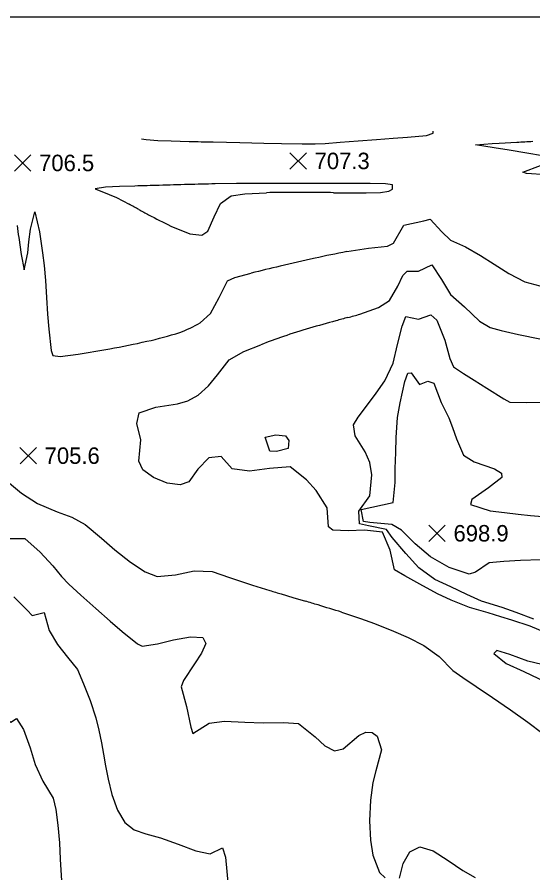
# Model space of a CAD drawing. Extents: x 2566079 to 2571326, y 424054 to 426896.
# Drawn here: x 2567271 to 2567741, y 426094 to 426874 of the extents above; entities that cross this region are included whole.
import ezdxf

# ---------------------------------------------------------------- set-up
doc = ezdxf.new("R2010")
doc.units = 0
for name, color, linetype in [('Contour_ADS_Major', 7, 'Continuous'), ('Contour_ADS_Minor', 7, 'Continuous'), ('Contour_ADS_Spot_Elevation', 7, 'Continuous'), ('Contour_ADS_State_Plane_Border', 7, 'Continuous')]:
    doc.layers.add(name, color=color, linetype=linetype)

# ---------------------------------------------------------------- blocks, each defined once
blk = doc.blocks.new('S750')
at = {"layer": 'Contour_ADS_Spot_Elevation'}
for p, q in [((-0.5, 0.498), (0.5, -0.498)), ((-0.498, -0.5), (0.498, 0.5))]:
    blk.add_line(p, q, dxfattribs=at)

msp = doc.modelspace()

# ---------------------------------------------------------------- linework, layer by layer
at = {"layer": 'Contour_ADS_Major'}
for points in [[(2567748.41, 426379.26), (2567729.86, 426378.59), (2567714.78, 426377.68), (2567701.34, 426376.28), (2567688.89, 426367.92), (2567683.13, 426366.09), (2567664.8, 426372.2), (2567648.02, 426381.8), (2567633.96, 426393.79), (2567621.58, 426406.17), (2567612.59, 426411.45), (2567592.69, 426413.15), (2567586.82, 426414.17), (2567584.76, 426424.92), (2567604.26, 426429.16), (2567614.04, 426431.53), (2567615.6, 426449.49), (2567615.84, 426462.31), (2567616.24, 426477.04), (2567616.73, 426490.71), (2567617.98, 426508.85), (2567620.14, 426522.36), (2567624.39, 426541.56), (2567627.16, 426549.24), (2567630.41, 426549.57), (2567637.76, 426539.03), (2567645.55, 426542.01), (2567650.8, 426540.1), (2567657.55, 426522.56), (2567664.63, 426508.58), (2567668.06, 426499.63), (2567671.74, 426489.33), (2567678, 426474.51), (2567687.66, 426468.49), (2567706.3, 426461.96), (2567712.56, 426458.11), (2567712.87, 426454.04), (2567700.6, 426444.81), (2567685.64, 426434.17), (2567684.49, 426429.59), (2567702.15, 426423.9), (2567715.37, 426422.15), (2567727.71, 426420.68), (2567739.05, 426419.5), (2567749.91, 426418.72)], [(2567268.29, 426345.26), (2567280.58, 426333.38), (2567284.99, 426328.32), (2567295.82, 426331.06), (2567300.41, 426314.84), (2567308.06, 426302), (2567317.11, 426290.53), (2567326.3, 426279.11), (2567331.89, 426266), (2567337.97, 426250.85), (2567343.07, 426235.01), (2567345.79, 426223.82), (2567348.15, 426212.42), (2567349.95, 426201.91), (2567351.71, 426191.36), (2567354.11, 426179.35), (2567357.74, 426165.16), (2567362.82, 426150.97), (2567369.48, 426139.68), (2567377.92, 426133.21), (2567388.58, 426129.56), (2567401.97, 426125.78), (2567417.99, 426119.91), (2567434.11, 426114.04), (2567447.18, 426111.28), (2567458.53, 426116.64), (2567461.16, 426108.06), (2567462.34, 426095.16), (2567463.66, 426081.33)]]:
    msp.add_lwpolyline(points, dxfattribs=at)
at = {"layer": 'Contour_ADS_Minor'}
for points in [[(2567439.01, 426760.22), (2567449.96, 426759.97), (2567462.05, 426759.7), (2567474.13, 426759.42), (2567485.11, 426759.18), (2567496.09, 426758.93), (2567512.31, 426758.56), (2567530.95, 426758.13), (2567542.91, 426758.18), (2567551.98, 426758.7), (2567565.51, 426759.71), (2567581.91, 426761), (2567598.77, 426762.31), (2567614.03, 426763.42), (2567626.94, 426764.34), (2567644.18, 426765.85), (2567650.33, 426767.9), (2567650.27, 426769.9)], [(2567384.57, 426762.75), (2567388.75, 426762.28), (2567399.59, 426761.44), (2567411.79, 426760.91), (2567428.07, 426760.48)], [(2567750.01, 426747.43), (2567735.7, 426749.77), (2567719.59, 426752.41), (2567705.95, 426754.66), (2567688.79, 426757.36), (2567704.02, 426758.63), (2567710.41, 426758.93), (2567726.65, 426759.79)], [(2567753.18, 426729.87), (2567735.26, 426731.27), (2567731.91, 426732.44), (2567748.19, 426738.36)], [(2567538.47, 426722.14), (2567510.23, 426722.14), (2567488.88, 426722.13), (2567471.17, 426722.04), (2567451.73, 426721.73)], [(2567570.82, 426713.59), (2567589.2, 426713.49), (2567602.43, 426713.95), (2567610.01, 426715.2), (2567613.32, 426716.88), (2567613.43, 426721.04), (2567606.86, 426721.81), (2567593.05, 426722.03)], [(2567351.86, 426718.71), (2567342.34, 426717.13), (2567355.31, 426712.17), (2567361.86, 426709.23), (2567373.32, 426703.27)], [(2567378.56, 426719.76), (2567364.48, 426719.3), (2567351.86, 426718.71), (2567351.86, 426718.71)], [(2567411.21, 426683.35), (2567428.63, 426676.2), (2567439.45, 426675.07), (2567445.06, 426678.72), (2567450.86, 426691.71), (2567456.61, 426703.77), (2567466.41, 426710.9), (2567478.61, 426712.73), (2567498.4, 426713.69)], [(2567272.78, 426672.96), (2567275.05, 426657.54), (2567277.86, 426643.44), (2567281, 426659.03), (2567282.06, 426668.96), (2567283.63, 426680.53), (2567287.37, 426696.3), (2567291.8, 426678.17), (2567294.57, 426658.99), (2567295.86, 426647.5), (2567297.02, 426633.59), (2567298.08, 426618.31), (2567299.11, 426603.13), (2567300.15, 426589.39), (2567302.2, 426569.78), (2567303.96, 426565.3), (2567310.57, 426564.35), (2567326.95, 426566.55)], [(2567571.66, 426660.01), (2567591.33, 426663.3), (2567608.83, 426665.08), (2567614.11, 426667.76), (2567623.57, 426684.16), (2567641.95, 426688.09), (2567647.61, 426689.6), (2567658.23, 426678.11), (2567666.07, 426670.45), (2567679.69, 426664.46), (2567693.58, 426656.61), (2567706.02, 426648.69), (2567719.36, 426640.03), (2567733.94, 426632.57), (2567747.41, 426628.8)], [(2567583.59, 426602.97), (2567600.43, 426609), (2567610.48, 426615.58), (2567618.04, 426628.65), (2567622.6, 426638.2), (2567626.73, 426642.12), (2567637.1, 426642.18), (2567649.1, 426648.04), (2567657.78, 426634.56), (2567666.18, 426620.87), (2567678.8, 426609.65), (2567692.69, 426596.54), (2567702.4, 426590.78), (2567712.14, 426588.18), (2567728.22, 426584.49), (2567747.65, 426580.49)], [(2567438.05, 426595.09), (2567447.49, 426603.68), (2567455.48, 426618.36), (2567462.96, 426633.49), (2567469.74, 426636.53), (2567484.53, 426640.41)], [(2567742.13, 426324.92), (2567725.89, 426331.26), (2567713.1, 426335.83), (2567694.49, 426341.61), (2567681.09, 426347.62), (2567666.33, 426354.48), (2567651.94, 426361.2), (2567637.29, 426371.7), (2567625.38, 426384.81), (2567612.9, 426399.63), (2567607.77, 426406.88), (2567591.43, 426410.26), (2567583.27, 426411.96), (2567582.75, 426423.56), (2567592.76, 426437.33), (2567594.52, 426456.7), (2567592.55, 426467.75), (2567588.44, 426477.54), (2567579.2, 426492.1), (2567577.9, 426502.06), (2567582.02, 426509.05), (2567589.47, 426519.22), (2567598.32, 426531.05), (2567606.15, 426542.29), (2567613.79, 426558.3), (2567617.92, 426575.45), (2567622.16, 426591.95), (2567625.5, 426600.98), (2567636.97, 426598.54), (2567648.28, 426602.53), (2567653.55, 426597.63), (2567660.99, 426579.18), (2567665.55, 426562.51), (2567668.95, 426554.89), (2567677.93, 426548.84), (2567687.83, 426542.73), (2567699.23, 426535.69), (2567714.82, 426525.91), (2567720.13, 426522.97), (2567735.53, 426522.64), (2567753.99, 426522.78)], [(2567721.92, 426324.22), (2567711.96, 426327.25), (2567700.38, 426330.76), (2567683.31, 426335.75), (2567666.76, 426342.23), (2567654.41, 426348.24), (2567638.04, 426357.09), (2567624.61, 426364.54), (2567615.04, 426370.01), (2567611.06, 426387.94), (2567604.1, 426404.49), (2567587.86, 426406.29), (2567572.88, 426405.48), (2567558.9, 426406.26), (2567555.06, 426409.12), (2567553.7, 426426.58), (2567543.89, 426442.35), (2567534.95, 426452.07), (2567520.14, 426463.98), (2567501.38, 426462.28), (2567482.87, 426459.84), (2567467.29, 426462.09), (2567457.26, 426473.26), (2567445.9, 426472.07), (2567435.82, 426461.8), (2567427.8, 426450.15), (2567419.87, 426447.36), (2567408.12, 426449.01), (2567395.52, 426454.18), (2567385.93, 426461.29), (2567382.11, 426468.96), (2567384.05, 426488.64), (2567380.22, 426503.49), (2567382.57, 426513.09), (2567397.67, 426518.36), (2567417.34, 426521.29), (2567426.8, 426523.92), (2567436.21, 426529.18), (2567445.56, 426537.78), (2567453.98, 426547.7), (2567464.43, 426561.48), (2567477.71, 426568.91), (2567493.19, 426575.08)], [(2567264.36, 426449.13), (2567275.36, 426439.79), (2567290.01, 426430.45), (2567307.92, 426422.99), (2567321.1, 426417.87), (2567333.34, 426411.25), (2567348.11, 426398.86), (2567360.47, 426388.28), (2567374.68, 426377), (2567388.11, 426368.16), (2567398.8, 426364.06), (2567415.45, 426365.38), (2567432.51, 426369.01), (2567448.95, 426368.38), (2567464.89, 426363.09), (2567474.04, 426359.85), (2567485.69, 426356.03), (2567501.55, 426351.13)], [(2567263.65, 426398.72), (2567278.2, 426398.68), (2567292.29, 426386.01), (2567303.71, 426373.55), (2567311.77, 426363.83), (2567318.49, 426357.04), (2567329.48, 426346.88), (2567342.87, 426334.92), (2567356.05, 426323.33), (2567366.9, 426313.9), (2567381.06, 426302.49), (2567385.29, 426300.41), (2567399.33, 426302.67), (2567413.72, 426306.18), (2567429.32, 426308.92), (2567440.49, 426308.35), (2567443.12, 426302.79), (2567439.38, 426293.93), (2567432.96, 426284.29), (2567422.79, 426269.03), (2567420.72, 426263.25), (2567425.66, 426245.37), (2567429.48, 426226.75), (2567431.4, 426220.85), (2567446.23, 426230.38), (2567460.22, 426232.02), (2567478.67, 426231.22), (2567495.52, 426230.61), (2567514.07, 426230.84), (2567527.6, 426229.83), (2567542.75, 426217.76), (2567551.64, 426209.5), (2567560.41, 426204.94), (2567568.43, 426206.92), (2567582.57, 426218.97), (2567589.01, 426222.03), (2567594.7, 426221.73), (2567599.17, 426218.47), (2567603.19, 426205.94), (2567597.98, 426186.69), (2567595.23, 426176.07), (2567593.24, 426160.09), (2567592.42, 426141.38), (2567593.09, 426123.65), (2567595.35, 426109.9), (2567601.46, 426094.19), (2567606.62, 426089.26)], [(2567511.98, 426348.01), (2567522.4, 426344.89), (2567533.92, 426341.45)], [(2567566.94, 426331.36), (2567583.98, 426325.72), (2567596.84, 426321.09), (2567614.28, 426314.25), (2567627.48, 426308.45), (2567641.82, 426301.21), (2567655.94, 426291.07), (2567668.17, 426278.21), (2567677.26, 426271.84), (2567689.64, 426263.59), (2567704.46, 426253.7), (2567720.7, 426242.57), (2567736.63, 426231.22), (2567750.32, 426220.82)], [(2568014.15, 426207.92), (2567996.8, 426215.66), (2567985.22, 426221.54), (2567972.59, 426229.14), (2567960.08, 426234.99), (2567944.64, 426241.19), (2567934.97, 426245.11), (2567922.77, 426250.15), (2567907.73, 426256.46), (2567891.99, 426263.09), (2567878.38, 426268.83), (2567860.77, 426275.82), (2567851.45, 426278.88), (2567838.34, 426282.91), (2567821.98, 426287.98), (2567803.67, 426293.95), (2567784.86, 426300.54), (2567767.69, 426306.87), (2567754.48, 426311.92), (2567738.55, 426318.56), (2567721.92, 426324.22), (2567721.92, 426324.22)], [(2567783.98, 426277.93), (2567766.83, 426281.13), (2567749.22, 426283.8), (2567736.59, 426286.73), (2567720.23, 426292.91), (2567708.45, 426296.59), (2567705.51, 426293.76), (2567716.85, 426284.8), (2567733, 426277.37), (2567746.39, 426271.11), (2567753.43, 426267.6), (2567766.94, 426260.94)], [(2567246.02, 426227.22), (2567260.29, 426234.98), (2567265.45, 426231.12), (2567270.63, 426234.47), (2567276.99, 426224.58), (2567283.12, 426207.93), (2567287.63, 426192.52), (2567294.86, 426177.28), (2567304.09, 426161.8), (2567306.68, 426151.66), (2567308.54, 426137.36), (2567309.79, 426121.24), (2567310.64, 426106.44), (2567311.82, 426086.51), (2567313.44, 426069.32), (2567317.06, 426059.43), (2567325.67, 426049.24), (2567340.46, 426039.34), (2567357.71, 426030.67), (2567372.46, 426024.26), (2567387.1, 426019.15), (2567405.23, 426018.1), (2567416.59, 426017.44)], [(2567619.54, 426089.06), (2567623.1, 426102.39), (2567629.22, 426113), (2567638.28, 426117.51), (2567650.32, 426113.84), (2567663.91, 426105.17), (2567677.28, 426096), (2567688.74, 426089.58)]]:
    msp.add_lwpolyline(points, dxfattribs=at)
msp.add_lwpolyline([(2567497.34, 426491.06), (2567507.02, 426493.07), (2567515.69, 426492.03), (2567518.99, 426487.94), (2567518.25, 426480.72), (2567507.73, 426477.72), (2567501.44, 426478.04), (2567497.34, 426491.06)], close=True, dxfattribs=at)
for centre, radius, start, end in [((2567567.01, 432376.37), 5617.6, 268.58276, 268.69437), ((2567195.35, 436414.45), 9669.27, 273.149856, 273.236028), ((2567581.96, 420059.25), 6663.61, 91.653569, 91.749139), ((2567701.91, 416404.27), 10320.54, 91.672061, 91.733711), ((2567649.98, 418234.37), 8489.71, 91.504986, 91.682144), ((2567549.72, 422018.25), 4704.5, 91.1935, 91.49465), ((2567521.46, 389957.43), 36764.71, 89.950114, 89.973492), ((2567555.46, 418438.46), 8283.67, 89.909919, 90.013739), ((2567562.61, 421764.46), 4957.67, 89.64815, 89.93211), ((2567523.44, 425669.44), 1044.55, 90.0273, 91.37351), ((2567524.92, 424463.86), 2250.13, 89.40613, 90.05036), ((2567516.29, 423682.12), 3031.92, 89.18286, 89.39623), ((2567600.6, 429570.44), 2857, 269.17633, 269.40277), ((2566928.49, 425870.66), 943.99, 61.27389, 61.88604), ((2567814.1, 427484.36), 896.76, 241.20768, 241.85237), ((2567661.67, 427197.71), 572.1, 241.76937, 244.03638), ((2569231.9, 426946.58), 1978.13, 187.63674, 187.95072), ((2567793.44, 425520.86), 1160.54, 101.01701, 102.47689), ((2567978.9, 424661.29), 2039.88, 102.34691, 103.26318), ((2567895.28, 424992.6), 1698.24, 103.08172, 103.99684), ((2570266.6, 416740.96), 10220.43, 105.346047, 105.486078), ((2572848.93, 407390.73), 19920.69, 105.358758, 105.391303), ((2567508.01, 426857.15), 265.18, 284.11844, 286.56075), ((2567385.36, 426683.88), 103.24, 289.27351, 300.68609), ((2567708.54, 426020.05), 595.33, 106.67656, 109.07235), ((2567319.8, 426893.78), 323.11, 282.47393, 287.96159), ((2567723.59, 425977.83), 640.15, 109.11011, 111.09456), ((2567222.21, 427317.22), 757.64, 280.14232, 282.76292), ((2567201.49, 427392.3), 835.23, 278.63933, 280.63501), ((2568105.84, 428352.25), 2090.38, 253.19693, 253.49533), ((2566775.05, 423786.54), 2665.23, 73.19888, 73.4574), ((2567017.76, 424591.26), 1824.7, 72.48408, 73.19065)]:
    msp.add_arc(centre, radius, start, end, dxfattribs=at)
at = {"layer": 'Contour_ADS_State_Plane_Border'}
msp.add_lwpolyline([(2566079.33, 424077.11), (2571302.93, 424077.11), (2571302.93, 426873.74), (2566079.33, 426873.74), (2566079.33, 424077.11)], close=True, dxfattribs=at)

# ---------------------------------------------------------------- block references
at = {"layer": 'Contour_ADS_Spot_Elevation', "xscale": 15, "yscale": 15}
for p in [(2567276.33, 426740.85), (2567527.33, 426742.68), (2567281.41, 426474.1), (2567653.87, 426403.34)]:
    msp.add_blockref('S750', p, dxfattribs=at)

# ---------------------------------------------------------------- texts
at = {"layer": 'Contour_ADS_Spot_Elevation'}
for s, p in [('706.5', (2567291.33, 426733.35)), ('707.3', (2567542.33, 426735.18)), ('705.6', (2567296.41, 426466.6)), ('698.9', (2567668.87, 426395.84))]:
    msp.add_text(s, height=15, dxfattribs=at).set_placement(p)

doc.saveas('drawing.dxf')
